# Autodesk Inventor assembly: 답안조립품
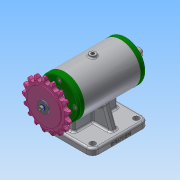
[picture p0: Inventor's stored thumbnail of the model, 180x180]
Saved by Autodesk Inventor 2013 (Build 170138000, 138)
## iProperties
Created: 2019-06
Part Number: 답안조립품
Document SubType Name: Assembly
Designer: Administrator
Author: Administrator
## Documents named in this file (11)
- C:\Users\Administrator\Desktop\490604V1024\답안조립품.iam
- C:\Users\Administrator\Desktop\490604V1024\본체.ipt
- C:\Users\Administrator\Desktop\490604V1024\베어링 6203.ipt
- C:\Users\Administrator\Desktop\490604V1024\볼트 M4.ipt
- C:\Users\Administrator\Desktop\490604V1024\스프로킷.ipt
- C:\Users\Administrator\Desktop\490604V1024\스프링와셔.ipt
- C:\Users\Administrator\Desktop\490604V1024\오일 실 17 30 5.ipt
- C:\Users\Administrator\Desktop\490604V1024\축.ipt
- C:\Users\Administrator\Desktop\490604V1024\커버.ipt
- C:\Users\Administrator\Desktop\490604V1024\키 4x4x12.ipt
- C:\Users\Administrator\Desktop\490604V1024\평와셔.ipt
